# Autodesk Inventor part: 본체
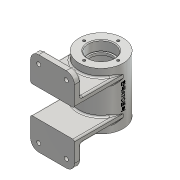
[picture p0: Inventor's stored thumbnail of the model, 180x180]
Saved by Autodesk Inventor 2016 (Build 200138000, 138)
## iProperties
Created: 2017-02
Part Number: 본체
Material: 알루미늄 6061
Document SubType Name: Modeling
Designer: H
Density: 2.7 g/cm^3
Appearance: 알루미늄 - 평지
Mass: 354.768 g
Surface Area: 422.772 cm^2
Volume: 131.396 cm^3
Author: H
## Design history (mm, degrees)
sketch "스케치1"
  geometry: C1 r 27 at (0, 0); 1 further point
  constraints: 1 centre point, 1 coincident
  dimensions: "d0" = 54 diameter of C1
extrude "돌출1" new body sketch "스케치1" stored distance "d1" = 70; taper "d2" = 0 deg
sketch "스케치2"
  geometry: L1 (0, 17)-(-60, 17); L2 (-60, 17)-(-60, 25); L3 (-52, 25)-(0, 25); L4 (0, 25)-(0, 17); L5 (-52, 25)-(-52, 52); L6 (-52, 52)-(-60, 52); L7 (-60, 52)-(-60, 25); 1 further point
  constraints: 14 end point, 3 parallel, 1 horizontal, 1 perpendicular
  dimensions: "d3" = 17 distance from line of L1 point (0, 0); "d5" = 60 distance of L1.start L1.end; "d6" = 60 distance from line of point (0, 0) L2; "d7" = 8 distance of L5.end L6.end; "d8" = 52 distance from line of point (0, 0) L6; "d9" = 8 distance of L3.end L1.start; "d10" = 90 deg angle of L3 L5; "d11" = 27 distance of L3.start L5.end; "d12" = 8 distance of L1.end L2.end
extrude "돌출2" join sketch "스케치2" stored distance "d13" = 54; taper "d14" = 0 deg
sketch "스케치3"
  geometry: C1 r 16 at (0, 0); 1 further point
  constraints: 1 centre point, 1 coincident
  dimensions: "d15" = 32 diameter of C1
extrude "돌출3" cut sketch "스케치3" distance "d16" = 12; taper "d17" = 0 deg
sketch "스케치4"
  geometry: C1 r 16 at (0, 0); 1 further point
  constraints: 1 centre point, 1 coincident
  dimensions: "d18" = 32 diameter of C1
extrude "돌출4" cut sketch "스케치4" distance "d19" = 12; taper "d20" = 0 deg
sketch "스케치5"
  geometry: C1 r 14 at (0, 0); 1 further point
  constraints: 1 centre point, 1 coincident
  dimensions: "d21" = 28 diameter of C1
extrude "돌출5" cut sketch "스케치5" distance "d22" = 3; taper "d23" = 0 deg
sketch "스케치6"
  geometry: C1 r 14 at (0, 0); 1 further point
  constraints: 1 centre point, 1 coincident
  dimensions: "d24" = 28 diameter of C1
extrude "돌출6" cut sketch "스케치6" distance "d25" = 3; taper "d26" = 0 deg
sketch "스케치7"
  geometry: C1 r 22 at (0, 0); 1 further point
  constraints: 1 centre point, 1 coincident
  dimensions: "d27" = 44 diameter of C1
extrude "돌출7" cut sketch "스케치7" stored distance "d28" = 3; taper "d29" = 0 deg
node "작업 평면1"
sketch "스케치8"
  geometry: L1 (54, 18)-(0, 18) reference; L2 (54, 8)-(54, 35) reference; C1 r 5 at (27, -7)
  constraints: 1 centre point
  dimensions: "d31" = 25 distance from line of C1.centre L1; "d32" = 10 diameter of C1; "d33" = 27 distance from line of C1.centre L2
extrude "돌출8" join sketch "스케치8" stored distance "d34" = 3; taper "d35" = 0 deg
sketch "스케치9"
  geometry: 1 further point
hole "구멍1" sketch "스케치9" at (0, 0) diameter "d36" = 5.188; stored, may be unused: countersink angle "d40" = 90 deg, drill point angle "d42" = 118 deg; dims "d37" = 12, "d38" = 4, "d39" = 2, "d41" = 14
sketch "스케치10"
  geometry: L1 (0, 0)-(48.075, 0); 1 further point
  constraints: 2 end point, 1 horizontal, 1 point on line
  dimensions: "d43" = 21 distance of L1.start point (21, 0)
hole "구멍2" sketch "스케치10" at (21, 0) diameter "d44" = 3.242; stored, may be unused: countersink angle "d48" = 90 deg, drill point angle "d50" = 118 deg; dims "d45" = 8, "d46" = 4, "d47" = 2, "d49" = 10
sketch "스케치11"
  geometry: L1 (0, 0)-(41.05, 0); 1 further point
  constraints: 2 end point, 1 horizontal, 1 point on line
  dimensions: "d54" = 21 distance of L1.start point (21, 0)
hole "구멍3" sketch "스케치11" at (21, 0) diameter "d55" = 3.242; stored, may be unused: countersink angle "d59" = 90 deg, drill point angle "d61" = 118 deg; dims "d56" = 8, "d57" = 4, "d58" = 2, "d60" = 10
fillet "모깎기1" dims "d65" = 10
sketch "스케치12" dims "d66" = 9
  geometry: L1 (39.5, -14.402)-(44, -11.804); L2 (44, -11.804)-(48.5, -14.402); L3 (48.5, -14.402)-(48.5, -19.598); L4 (48.5, -19.598)-(44, -22.196); L5 (44, -22.196)-(39.5, -19.598); L6 (39.5, -19.598)-(39.5, -14.402); A1 r 10 centre (44, -17) between (44, -27) and (54, -17) reference; 4 further points
  constraints: 12 end point, 1 coincident, 1 horizontal alignment, 1 midpoint, 16 other
  dimensions: "d67" = 2.59808 vertical distance of L1.end L2.end
extrude "돌출9" cut sketch "스케치12" distance "d68" = 3; taper "d69" = 0 deg
sketch "스케치13"
  geometry: C1 r 2.5 at (44, -17); A1 r 10 centre (44, -17) between (44, -27) and (54, -17) reference; 1 further point
  constraints: 1 centre point, 1 concentric
  dimensions: "d70" = 5 diameter of C1
extrude "돌출10" cut sketch "스케치13" stored distance "d71" = 3; taper "d72" = 0 deg
sketch "스케치14"
  geometry: L1 (0, 0)-(-16.339, -25.16); L2 (0, 0)-(0, -85.016)
  constraints: 4 end point, 1 vertical
  dimensions: "d73" = 33 deg angle of L1 L2; "d74" = 30 distance of L1.start L1.end
node "작업 평면2"
sketch "스케치15"
  geometry: C1 r 6 at (0, 0); 1 further point
  constraints: 1 centre point, 1 coincident
  dimensions: "d75" = 12 diameter of C1
extrude "돌출11" join sketch "스케치15" stored distance "d76" = 3; taper "d77" = 0 deg
sketch "스케치16"
  geometry: 2 further points
  constraints: 1 coincident
hole "구멍4" sketch "스케치16" at (0, 0) diameter "d78" = 5.188; stored, may be unused: countersink angle "d82" = 90 deg, drill point angle "d84" = 118 deg; dims "d79" = 12, "d80" = 4, "d81" = 2, "d83" = 16
node "작업 평면3"
sketch "스케치17"
  geometry: 2 further points
  constraints: 1 coincident, 1 other
feature "엠보싱1" sketch "스케치17" dims "d86" = 0.5, "d87" = 0
fillet "모깎기2" dims "d88" = 3
fillet "모깎기3" dims "d89" = 0.3
chamfer "모따기1" distance "d90" = 1; stored, may be unused: second distance "d91" = 2, angle "d92" = 45 deg
fillet "모깎기4" dims "d93" = 2
fillet "모깎기5" dims "d94" = 2
fillet "모깎기6" dims "d95" = 2
fillet "모깎기7" dims "d96" = 2
fillet "모깎기8" dims "d97" = 2
fillet "모깎기9" dims "d98" = 2
node "솔리드1"
mirror "대칭1"
pattern_circular "원형 패턴1" dims angle "d52" = 360 deg
pattern_circular "원형 패턴2" dims angle "d63" = 360 deg
mirror "대칭2"
mirror "대칭6"
mirror "대칭4"
mirror "대칭5"
other parameters: "d30" = -92
